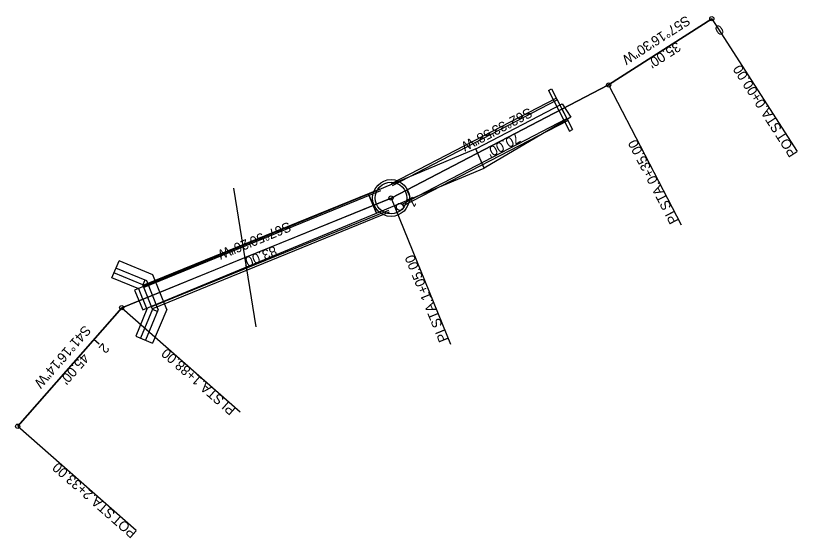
# Model space of a CAD drawing. Extents: x 195264 to 195488, y 337087 to 337236.
import ezdxf

# ---------------------------------------------------------------- set-up
doc = ezdxf.new("R2010")
doc.units = 0
for name, color, linetype in [('DR_P_Cells', 7, 'Continuous'), ('DR_P_Culvert', 7, 'Continuous'), ('DR_P_Headwall', 7, 'Continuous'), ('DR_X_Culvert', 7, 'Continuous'), ('GE_P_Alignment', 7, 'Continuous'), ('GE_P_Alignment_100_Bearings', 7, 'Continuous'), ('GE_P_Alignment_100_Cardinal_Points', 7, 'Continuous'), ('GE_P_Alignment_100_Distances', 7, 'Continuous'), ('GE_P_Alignment_100_Stations', 7, 'Continuous'), ('GK_Drainage_Nodes', 7, 'Continuous'), ('SC_Scratch1', 7, 'Continuous')]:
    doc.layers.add(name, color=color, linetype=linetype)

msp = doc.modelspace()

# ---------------------------------------------------------------- linework, layer by layer
at = {"layer": 'DR_P_Cells'}
for centre, radius in [((195371.62, 337183.96), 5.25), ((195371.62, 337183.96), 4.5), ((195374.15, 337181.43), 1)]:
    msp.add_circle(centre, radius, dxfattribs=at)
at = {"layer": 'DR_P_Culvert'}
for p, q in [((195371.74, 337188.06), (195418.78, 337212.48)), ((195372.01, 337187.55), (195419.05, 337211.96)), ((195374.77, 337182.22), (195421.81, 337206.64)), ((195375.04, 337181.7), (195422.08, 337206.12)), ((195368.41, 337186.53), (195300.81, 337158.99)), ((195368.63, 337185.99), (195301.03, 337158.45)), ((195370.9, 337180.43), (195303.29, 337152.89)), ((195371.12, 337179.89), (195303.51, 337152.35))]:
    msp.add_line(p, q, dxfattribs=at)
at = {"layer": 'DR_P_Headwall'}
for p, q in [((195416.55, 337214.61), (195417.44, 337215.07)), ((195416.55, 337214.61), (195422.54, 337203.07)), ((195417.44, 337215.07), (195423.43, 337203.53)), ((195422.54, 337203.07), (195423.43, 337203.53)), ((195291.94, 337161.23), (195293.98, 337166.06)), ((195301.9, 337160.29), (195293.1, 337163.99)), ((195303.63, 337162), (195293.98, 337166.06)), ((195300.74, 337159.15), (195292.52, 337162.61)), ((195307.63, 337152.18), (195303.63, 337162)), ((195299.59, 337158.01), (195291.94, 337161.23)), ((195301.32, 337160.53), (195300.74, 337159.15)), ((195305.19, 337152.19), (195301.9, 337160.29)), ((195300.77, 337155.11), (195299.59, 337158.01)), ((195303.57, 337152.2), (195300.74, 337159.15)), ((195300.77, 337155.11), (195301.95, 337152.21)), ((195301.95, 337152.21), (195298.73, 337144.56)), ((195303.57, 337152.2), (195300.11, 337143.98)), ((195305.19, 337152.19), (195301.49, 337143.4)), ((195307.63, 337152.18), (195303.56, 337142.52)), ((195303.57, 337152.2), (195304.95, 337151.62)), ((195298.73, 337144.56), (195303.56, 337142.52))]:
    msp.add_line(p, q, dxfattribs=at)
at = {"layer": 'DR_X_Culvert'}
for p, q in [((195395.8, 337197.97), (195420.45, 337210.81)), ((195420.45, 337210.81), (195422.95, 337207.04)), ((195422.95, 337207.04), (195398.24, 337192.5)), ((195395.8, 337197.97), (195365.23, 337185.06)), ((195398.24, 337192.5), (195395.8, 337197.97)), ((195398.24, 337192.5), (195395.8, 337197.97)), ((195367.52, 337179.62), (195398.24, 337192.5)), ((195365.23, 337185.06), (195298.41, 337157.71)), ((195367.52, 337179.62), (195365.23, 337185.06)), ((195365.23, 337185.06), (195367.52, 337179.62)), ((195300.79, 337152.03), (195367.52, 337179.62)), ((195298.41, 337157.71), (195300.79, 337152.03))]:
    msp.add_line(p, q, dxfattribs=at)
at = {"layer": 'GE_P_Alignment'}
for p, q in [((195463.19, 337235.13), (195433.75, 337216.21)), ((195433.75, 337216.21), (195371.62, 337183.96)), ((195371.62, 337183.96), (195294.75, 337152.66)), ((195294.75, 337152.66), (195265.06, 337118.83))]:
    msp.add_line(p, q, dxfattribs=at)
at = {"layer": 'GE_P_Alignment_100_Cardinal_Points'}
for p, q in [((195463.19, 337235.13), (195487.52, 337197.28)), ((195433.75, 337216.21), (195454.48, 337176.27)), ((195371.62, 337183.96), (195388.59, 337142.29)), ((195294.75, 337152.66), (195328.57, 337122.97)), ((195265.06, 337118.83), (195298.89, 337089.15))]:
    msp.add_line(p, q, dxfattribs=at)
for centre in [(195463.19, 337235.13), (195433.75, 337216.21), (195371.62, 337183.96), (195294.75, 337152.66), (195265.06, 337118.83)]:
    msp.add_circle(centre, 0.6, dxfattribs=at)
at = {"layer": 'GE_P_Alignment_100_Stations'}
for p, q in [((195463.19, 337235.13), (195464.27, 337233.45)), ((195420.43, 337209.3), (195420.98, 337208.24)), ((195376.05, 337186.27), (195376.98, 337184.49)), ((195329.94, 337166.99), (195330.39, 337165.88)), ((195286.83, 337143.64), (195288.34, 337142.32))]:
    msp.add_line(p, q, dxfattribs=at)
at = {"layer": 'GK_Drainage_Nodes'}
for p, q in [((195368.44, 337187.14), (195368.44, 337187.14)), ((195371.62, 337183.96), (195371.62, 337183.96)), ((195371.62, 337183.96), (195371.62, 337183.96)), ((195374.15, 337181.43), (195374.15, 337181.43)), ((195374.8, 337180.78), (195374.8, 337180.78))]:
    msp.add_line(p, q, dxfattribs=at)
msp.add_circle((195371.62, 337183.96), 4.5, dxfattribs=at)
at = {"layer": 'SC_Scratch1'}
for p, q in [((195433.75, 337216.21), (195463.19, 337235.13)), ((195371.62, 337183.96), (195433.75, 337216.21)), ((195333.12, 337147.24), (195326.76, 337186.73)), ((195329.94, 337166.99), (195371.62, 337183.96)), ((195294.75, 337152.66), (195329.94, 337166.99)), ((195265.06, 337118.83), (195294.75, 337152.66))]:
    msp.add_line(p, q, dxfattribs=at)

# ---------------------------------------------------------------- texts
at = {"layer": 'GE_P_Alignment_100_Bearings'}
for s, rotation, p in [('S57°16\'30"W', 212.7249, (195455.88, 337236.14)), ('S62°33\'58"W', 207.4338, (195411.02, 337209.83)), ('S67°50\'26"W', 202.1593, (195342.38, 337177.24)), ('S41°16\'14"W', 228.7294, (195284.14, 337147.85))]:
    msp.add_text(s, height=2.8, rotation=rotation, dxfattribs=at).set_placement(p)
at = {"layer": 'GE_P_Alignment_100_Cardinal_Points'}
for s, rotation, p in [('0+00.00', 122.7249, (195478.78, 337210.79)), (' STA. ', 122.7249, (195483.89, 337202.84)), ('POT', 122.7249, (195487.79, 337196.78)), ('0+35.00', 117.4338, (195447.91, 337188.84)), (' STA. ', 117.4338, (195452.26, 337180.45)), ('PI', 117.4338, (195453.82, 337177.44)), ('1+05.00', 112.1593, (195383.2, 337155.41)), (' STA. ', 112.1593, (195386.77, 337146.65)), ('PI', 112.1593, (195388.05, 337143.51)), ('1+88.00', 138.7294, (195317.88, 337132.3)), (' STA. ', 138.7294, (195324.99, 337126.06)), ('PI', 138.7294, (195327.53, 337123.83)), ('2+33.00', 138.7294, (195286.77, 337099.73)), (' STA. ', 138.7294, (195293.87, 337093.5)), ('POT', 138.7294, (195299.28, 337088.75))]:
    msp.add_text(s, height=2.8, rotation=rotation, dxfattribs=at).set_placement(p)
at = {"layer": 'GE_P_Alignment_100_Distances'}
for s, rotation, p in [("35.00'", 212.7249, (195453.17, 337228.64)), ("70.00'", 207.4338, (195407.64, 337202.61)), ("83.00'", 202.1593, (195338.35, 337170.37)), ("45.00'", 228.7294, (195283.61, 337139.9))]:
    msp.add_text(s, height=2.8, rotation=rotation, dxfattribs=at).set_placement(p)
at = {"layer": 'GE_P_Alignment_100_Stations'}
for s, rotation, p in [('0', 212.7249, (195465.48, 337233.63)), ('1', 207.4338, (195378.02, 337184.47)), ('2', 228.7294, (195289.4, 337142.77))]:
    msp.add_text(s, height=2.8, rotation=rotation, dxfattribs=at).set_placement(p)

doc.saveas('drawing.dxf')
